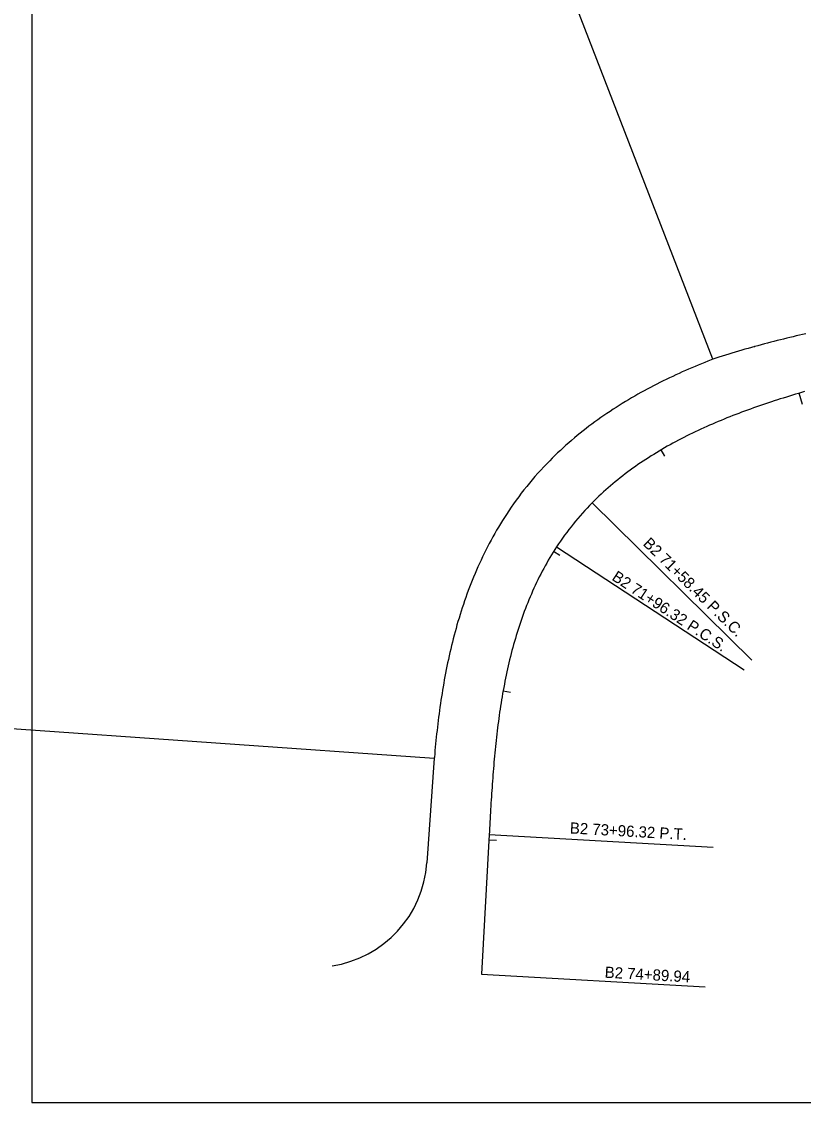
# Model space of a CAD drawing. Extents: x 7583978 to 7589962, y 550226 to 553847.
# Drawn here: x 7588230 to 7588753, y 550226 to 550949 of the extents above; entities that cross this region are included whole.
import ezdxf

# ---------------------------------------------------------------- set-up
doc = ezdxf.new("R2010")
doc.units = 0
for name, color, linetype in [('#plot_shape', 7, 'Continuous'), ('Default', 7, 'Continuous'), ('P_RDWY_ALIGN_Main', 7, 'Continuous'), ('P_RDWY_ALIGN_MainTx', 7, 'Continuous'), ('P_RDWY_ALIGN_Ramp', 7, 'Continuous'), ('P_RDWY_ALIGN_RampTic', 7, 'Continuous'), ('P_RDWY_ALIGN_RampTx', 7, 'Continuous')]:
    doc.layers.add(name, color=color, linetype=linetype)

msp = doc.modelspace()

# ---------------------------------------------------------------- linework, layer by layer
at = {"layer": '#plot_shape'}
msp.add_lwpolyline([(7588237.1, 551265.36), (7588237.1, 550226.04), (7589430.93, 550226.04), (7589430.93, 550741.48), (7589962.46, 551428.79), (7589291.08, 551428.4), (7589291.08, 551261.86)], close=True, dxfattribs=at)
at = {"layer": 'Default'}
for p, q in [((7588692.65, 550723.11), (7588512.21, 551189.41)), ((7588007.56, 550491.18), (7588506.35, 550456.35))]:
    msp.add_line(p, q, dxfattribs=at)
at = {"layer": 'P_RDWY_ALIGN_Main'}
for p, q in [((7588744.17, 550737.67), (7588742.04, 550737.15)), ((7588746.29, 550738.19), (7588744.17, 550737.67)), ((7588748.42, 550738.7), (7588746.29, 550738.19)), ((7588750.53, 550739.2), (7588748.42, 550738.7)), ((7588752.65, 550739.7), (7588750.53, 550739.2)), ((7588754.76, 550740.2), (7588752.65, 550739.7)), ((7588716.27, 550730.36), (7588714.1, 550729.75)), ((7588718.43, 550730.97), (7588716.27, 550730.36)), ((7588720.59, 550731.57), (7588718.43, 550730.97)), ((7588722.75, 550732.16), (7588720.59, 550731.57)), ((7588724.9, 550732.75), (7588722.75, 550732.16)), ((7588727.06, 550733.32), (7588724.9, 550732.75)), ((7588729.21, 550733.89), (7588727.06, 550733.32)), ((7588731.35, 550734.45), (7588729.21, 550733.89)), ((7588733.5, 550735), (7588731.35, 550734.45)), ((7588735.64, 550735.55), (7588733.5, 550735)), ((7588737.78, 550736.09), (7588735.64, 550735.55)), ((7588739.91, 550736.62), (7588737.78, 550736.09)), ((7588742.04, 550737.15), (7588739.91, 550736.62)), ((7588692.65, 550723.11), (7588691.45, 550722.64)), ((7588694.53, 550723.73), (7588692.65, 550723.11)), ((7588696.71, 550724.44), (7588694.53, 550723.73)), ((7588698.89, 550725.14), (7588696.71, 550724.44)), ((7588701.07, 550725.83), (7588698.89, 550725.14)), ((7588703.25, 550726.51), (7588701.07, 550725.83)), ((7588705.42, 550727.18), (7588703.25, 550726.51)), ((7588707.59, 550727.83), (7588705.42, 550727.18)), ((7588709.76, 550728.48), (7588707.59, 550727.83)), ((7588711.93, 550729.12), (7588709.76, 550728.48)), ((7588714.1, 550729.75), (7588711.93, 550729.12)), ((7588676.45, 550716.48), (7588674.31, 550715.55)), ((7588678.59, 550717.4), (7588676.45, 550716.48)), ((7588680.73, 550718.31), (7588678.59, 550717.4)), ((7588682.87, 550719.2), (7588680.73, 550718.31)), ((7588685.02, 550720.08), (7588682.87, 550719.2)), ((7588687.16, 550720.95), (7588685.02, 550720.08)), ((7588689.3, 550721.8), (7588687.16, 550720.95)), ((7588691.45, 550722.64), (7588689.3, 550721.8)), ((7588659.37, 550708.6), (7588657.25, 550707.54)), ((7588661.5, 550709.63), (7588659.37, 550708.6)), ((7588663.63, 550710.66), (7588661.5, 550709.63)), ((7588665.76, 550711.67), (7588663.63, 550710.66)), ((7588667.9, 550712.66), (7588665.76, 550711.67)), ((7588670.03, 550713.64), (7588667.9, 550712.66)), ((7588672.17, 550714.6), (7588670.03, 550713.64)), ((7588674.31, 550715.55), (7588672.17, 550714.6)), ((7588646.68, 550702.01), (7588644.57, 550700.85)), ((7588648.78, 550703.15), (7588646.68, 550702.01)), ((7588650.89, 550704.27), (7588648.78, 550703.15)), ((7588653.01, 550705.38), (7588650.89, 550704.27)), ((7588655.13, 550706.47), (7588653.01, 550705.38)), ((7588657.25, 550707.54), (7588655.13, 550706.47)), ((7588634.14, 550694.79), (7588632.07, 550693.53)), ((7588636.21, 550696.04), (7588634.14, 550694.79)), ((7588638.3, 550697.27), (7588636.21, 550696.04)), ((7588640.38, 550698.49), (7588638.3, 550697.27)), ((7588642.48, 550699.68), (7588640.38, 550698.49)), ((7588644.57, 550700.85), (7588642.48, 550699.68)), ((7588621.82, 550686.89), (7588619.79, 550685.51)), ((7588623.85, 550688.26), (7588621.82, 550686.89)), ((7588625.89, 550689.61), (7588623.85, 550688.26)), ((7588627.95, 550690.93), (7588625.89, 550689.61)), ((7588630, 550692.24), (7588627.95, 550690.93)), ((7588632.07, 550693.53), (7588630, 550692.24)), ((7588611.77, 550679.75), (7588609.79, 550678.26)), ((7588613.76, 550681.22), (7588611.77, 550679.75)), ((7588615.76, 550682.67), (7588613.76, 550681.22)), ((7588617.77, 550684.1), (7588615.76, 550682.67)), ((7588619.79, 550685.51), (7588617.77, 550684.1)), ((7588603.91, 550673.66), (7588601.98, 550672.08)), ((7588605.86, 550675.22), (7588603.91, 550673.66)), ((7588607.82, 550676.75), (7588605.86, 550675.22)), ((7588609.79, 550678.26), (7588607.82, 550676.75)), ((7588594.36, 550665.55), (7588592.49, 550663.87)), ((7588596.24, 550667.22), (7588594.36, 550665.55)), ((7588598.14, 550668.86), (7588596.24, 550667.22)), ((7588600.05, 550670.49), (7588598.14, 550668.86)), ((7588601.98, 550672.08), (7588600.05, 550670.49)), ((7588586.96, 550658.66), (7588585.15, 550656.89)), ((7588588.79, 550660.42), (7588586.96, 550658.66)), ((7588590.63, 550662.16), (7588588.79, 550660.42)), ((7588592.49, 550663.87), (7588590.63, 550662.16)), ((7588585.15, 550656.89), (7588583.51, 550655.24)), ((7588551.91, 550615.21), (7588550.58, 550613.05)), ((7588553.26, 550617.35), (7588551.91, 550615.21)), ((7588554.52, 550619.3), (7588553.26, 550617.35)), ((7588547.99, 550608.7), (7588546.74, 550606.52)), ((7588549.27, 550610.88), (7588547.99, 550608.7)), ((7588550.58, 550613.05), (7588549.27, 550610.88)), ((7588543.13, 550599.91), (7588541.97, 550597.69)), ((7588544.31, 550602.12), (7588543.13, 550599.91)), ((7588545.51, 550604.32), (7588544.31, 550602.12)), ((7588546.74, 550606.52), (7588545.51, 550604.32)), ((7588539.73, 550593.23), (7588538.65, 550590.99)), ((7588540.84, 550595.46), (7588539.73, 550593.23)), ((7588541.97, 550597.69), (7588540.84, 550595.46)), ((7588536.55, 550586.49), (7588535.53, 550584.24)), ((7588537.59, 550588.74), (7588536.55, 550586.49)), ((7588538.65, 550590.99), (7588537.59, 550588.74)), ((7588533.57, 550579.71), (7588532.62, 550577.44)), ((7588534.54, 550581.97), (7588533.57, 550579.71)), ((7588535.53, 550584.24), (7588534.54, 550581.97)), ((7588530.79, 550572.88), (7588529.91, 550570.6)), ((7588531.7, 550575.16), (7588530.79, 550572.88)), ((7588532.62, 550577.44), (7588531.7, 550575.16)), ((7588528.2, 550566.03), (7588527.38, 550563.74)), ((7588529.05, 550568.32), (7588528.2, 550566.03)), ((7588529.91, 550570.6), (7588529.05, 550568.32)), ((7588525.04, 550556.86), (7588524.3, 550554.56)), ((7588525.8, 550559.16), (7588525.04, 550556.86)), ((7588526.58, 550561.45), (7588525.8, 550559.16)), ((7588527.38, 550563.74), (7588526.58, 550561.45)), ((7588522.87, 550549.97), (7588522.18, 550547.67)), ((7588523.57, 550552.27), (7588522.87, 550549.97)), ((7588524.3, 550554.56), (7588523.57, 550552.27)), ((7588520.86, 550543.07), (7588520.23, 550540.77)), ((7588521.51, 550545.37), (7588520.86, 550543.07)), ((7588522.18, 550547.67), (7588521.51, 550545.37)), ((7588519.02, 550536.16), (7588518.44, 550533.87)), ((7588519.62, 550538.46), (7588519.02, 550536.16)), ((7588520.23, 550540.77), (7588519.62, 550538.46)), ((7588517.32, 550529.27), (7588516.79, 550526.97)), ((7588517.87, 550531.57), (7588517.32, 550529.27)), ((7588518.44, 550533.87), (7588517.87, 550531.57)), ((7588515.77, 550522.38), (7588515.28, 550520.09)), ((7588516.27, 550524.68), (7588515.77, 550522.38)), ((7588516.79, 550526.97), (7588516.27, 550524.68)), ((7588513.9, 550513.22), (7588513.47, 550510.94)), ((7588514.34, 550515.51), (7588513.9, 550513.22)), ((7588514.8, 550517.8), (7588514.34, 550515.51)), ((7588515.28, 550520.09), (7588514.8, 550517.8)), ((7588512.64, 550506.37), (7588512.25, 550504.09)), ((7588513.05, 550508.65), (7588512.64, 550506.37)), ((7588513.47, 550510.94), (7588513.05, 550508.65)), ((7588511.5, 550499.54), (7588511.14, 550497.27)), ((7588511.87, 550501.82), (7588511.5, 550499.54)), ((7588512.25, 550504.09), (7588511.87, 550501.82)), ((7588510.46, 550492.74), (7588510.14, 550490.48)), ((7588510.8, 550495.01), (7588510.46, 550492.74)), ((7588511.14, 550497.27), (7588510.8, 550495.01)), ((7588509.52, 550485.97), (7588509.23, 550483.72)), ((7588509.83, 550488.23), (7588509.52, 550485.97)), ((7588510.14, 550490.48), (7588509.83, 550488.23)), ((7588508.68, 550479.23), (7588508.41, 550476.99)), ((7588508.95, 550481.47), (7588508.68, 550479.23)), ((7588509.23, 550483.72), (7588508.95, 550481.47)), ((7588507.67, 550470.29), (7588507.44, 550468.06)), ((7588507.91, 550472.52), (7588507.67, 550470.29)), ((7588508.16, 550474.75), (7588507.91, 550472.52)), ((7588508.41, 550476.99), (7588508.16, 550474.75)), ((7588507, 550463.62), (7588506.8, 550461.41)), ((7588507.22, 550465.84), (7588507, 550463.62)), ((7588507.44, 550468.06), (7588507.22, 550465.84)), ((7588506.35, 550456.35), (7588501.45, 550386.26)), ((7588506.4, 550456.99), (7588506.35, 550456.35)), ((7588506.59, 550459.2), (7588506.4, 550456.99)), ((7588506.8, 550461.41), (7588506.59, 550459.2))]:
    msp.add_line(p, q, dxfattribs=at)
for centre, radius, start, end in [((7588747.91, 550492.98), 230.99, 135.37515, 146.84604), ((7588426.63, 550391.48), 75, 278.68725, 356.00603)]:
    msp.add_arc(centre, radius, start, end, dxfattribs=at)
at = {"layer": 'P_RDWY_ALIGN_MainTx'}
for centre in [(7588744.17, 550737.67), (7588746.29, 550738.19), (7588748.42, 550738.7), (7588750.53, 550739.2), (7588752.65, 550739.7), (7588716.27, 550730.36), (7588718.43, 550730.97), (7588720.59, 550731.57), (7588722.75, 550732.16), (7588724.9, 550732.75), (7588727.06, 550733.32), (7588729.21, 550733.89), (7588731.35, 550734.45), (7588733.5, 550735), (7588735.64, 550735.55), (7588737.78, 550736.09), (7588739.91, 550736.62), (7588742.04, 550737.15), (7588692.65, 550723.11), (7588694.53, 550723.73), (7588696.71, 550724.44), (7588698.89, 550725.14), (7588701.07, 550725.83), (7588703.25, 550726.51), (7588705.42, 550727.18), (7588707.59, 550727.83), (7588709.76, 550728.48), (7588711.93, 550729.12), (7588714.1, 550729.75), (7588676.45, 550716.48), (7588678.59, 550717.4), (7588680.73, 550718.31), (7588682.87, 550719.2), (7588685.02, 550720.08), (7588687.16, 550720.95), (7588689.3, 550721.8), (7588691.45, 550722.64), (7588659.37, 550708.6), (7588661.5, 550709.63), (7588663.63, 550710.66), (7588665.76, 550711.67), (7588667.9, 550712.66), (7588670.03, 550713.64), (7588672.17, 550714.6), (7588674.31, 550715.55), (7588646.68, 550702.01), (7588648.78, 550703.15), (7588650.89, 550704.27), (7588653.01, 550705.38), (7588655.13, 550706.47), (7588657.25, 550707.54), (7588634.14, 550694.79), (7588636.21, 550696.04), (7588638.3, 550697.27), (7588640.38, 550698.49), (7588642.48, 550699.68), (7588644.57, 550700.85), (7588621.82, 550686.89), (7588623.85, 550688.26), (7588625.89, 550689.61), (7588627.95, 550690.93), (7588630, 550692.24), (7588632.07, 550693.53), (7588611.77, 550679.75), (7588613.76, 550681.22), (7588615.76, 550682.67), (7588617.77, 550684.1), (7588619.79, 550685.51), (7588603.91, 550673.66), (7588605.86, 550675.22), (7588607.82, 550676.75), (7588609.79, 550678.26), (7588594.36, 550665.55), (7588596.24, 550667.22), (7588598.14, 550668.86), (7588600.05, 550670.49), (7588601.98, 550672.08), (7588586.96, 550658.66), (7588588.79, 550660.42), (7588590.63, 550662.16), (7588592.49, 550663.87), (7588583.51, 550655.24), (7588585.15, 550656.89), (7588611.85, 550627.01), (7588551.91, 550615.21), (7588553.26, 550617.35), (7588554.52, 550619.3), (7588547.99, 550608.7), (7588549.27, 550610.88), (7588550.58, 550613.05), (7588543.13, 550599.91), (7588544.31, 550602.12), (7588545.51, 550604.32), (7588546.74, 550606.52), (7588539.73, 550593.23), (7588540.84, 550595.46), (7588541.97, 550597.69), (7588588.11, 550597.58), (7588536.55, 550586.49), (7588537.59, 550588.74), (7588538.65, 550590.99), (7588533.57, 550579.71), (7588534.54, 550581.97), (7588535.53, 550584.24), (7588530.79, 550572.88), (7588531.7, 550575.16), (7588532.62, 550577.44), (7588528.2, 550566.03), (7588529.05, 550568.32), (7588529.91, 550570.6), (7588525.04, 550556.86), (7588525.8, 550559.16), (7588526.58, 550561.45), (7588527.38, 550563.74), (7588522.87, 550549.97), (7588523.57, 550552.27), (7588524.3, 550554.56), (7588520.86, 550543.07), (7588521.51, 550545.37), (7588522.18, 550547.67), (7588519.02, 550536.16), (7588519.62, 550538.46), (7588520.23, 550540.77), (7588517.32, 550529.27), (7588517.87, 550531.57), (7588518.44, 550533.87), (7588515.77, 550522.38), (7588516.27, 550524.68), (7588516.79, 550526.97), (7588513.9, 550513.22), (7588514.34, 550515.51), (7588514.8, 550517.8), (7588515.28, 550520.09), (7588512.64, 550506.37), (7588513.05, 550508.65), (7588513.47, 550510.94), (7588511.5, 550499.54), (7588511.87, 550501.82), (7588512.25, 550504.09), (7588510.46, 550492.74), (7588510.8, 550495.01), (7588511.14, 550497.27), (7588509.52, 550485.97), (7588509.83, 550488.23), (7588510.14, 550490.48), (7588508.68, 550479.23), (7588508.95, 550481.47), (7588509.23, 550483.72), (7588507.67, 550470.29), (7588507.91, 550472.52), (7588508.16, 550474.75), (7588508.41, 550476.99), (7588507, 550463.62), (7588507.22, 550465.84), (7588507.44, 550468.06), (7588506.35, 550456.35), (7588506.35, 550456.35), (7588506.4, 550456.99), (7588506.59, 550459.2), (7588506.8, 550461.41), (7588543.05, 550405.22), (7588501.45, 550386.26), (7588437.96, 550317.34), (7588537.81, 550311.75)]:
    msp.add_circle(centre, 0.00187, dxfattribs=at)
at = {"layer": 'P_RDWY_ALIGN_Ramp'}
msp.add_line((7588543.05, 550405.22), (7588537.81, 550311.75), dxfattribs=at)
for points in [[(7588753.85, 550701.47), (7588751.83, 550700.87), (7588749.82, 550700.26), (7588747.8, 550699.65), (7588745.79, 550699.04), (7588743.78, 550698.42), (7588741.77, 550697.79), (7588739.76, 550697.16), (7588737.75, 550696.53), (7588735.75, 550695.88), (7588733.74, 550695.24), (7588731.74, 550694.58), (7588729.74, 550693.92), (7588727.75, 550693.25), (7588725.75, 550692.57), (7588723.76, 550691.89), (7588721.77, 550691.2), (7588719.79, 550690.5), (7588717.8, 550689.79), (7588715.82, 550689.08), (7588713.85, 550688.36), (7588711.87, 550687.62), (7588709.9, 550686.88), (7588707.94, 550686.13), (7588705.97, 550685.37), (7588704.01, 550684.6), (7588702.06, 550683.82), (7588700.11, 550683.03), (7588698.16, 550682.23), (7588696.21, 550681.43), (7588694.28, 550680.61), (7588692.34, 550679.77), (7588690.41, 550678.93), (7588688.49, 550678.08), (7588686.57, 550677.21), (7588684.65, 550676.34), (7588682.74, 550675.45), (7588680.84, 550674.55), (7588678.94, 550673.64), (7588677.05, 550672.71), (7588675.17, 550671.78), (7588673.29, 550670.83), (7588671.42, 550669.87), (7588669.55, 550668.89), (7588667.69, 550667.9), (7588665.84, 550666.9), (7588663.99, 550665.89), (7588662.16, 550664.86), (7588660.33, 550663.81), (7588658.51, 550662.76), (7588656.7, 550661.69), (7588654.89, 550660.6), (7588653.1, 550659.5), (7588651.31, 550658.39), (7588649.53, 550657.26), (7588647.77, 550656.11), (7588646.01, 550654.96), (7588644.26, 550653.78), (7588642.52, 550652.59), (7588640.8, 550651.39), (7588639.08, 550650.17), (7588637.37, 550648.94), (7588635.68, 550647.69), (7588634, 550646.42), (7588632.33, 550645.14), (7588630.67, 550643.84), (7588629.03, 550642.53), (7588627.39, 550641.2), (7588625.77, 550639.85), (7588624.17, 550638.49), (7588622.58, 550637.11), (7588621, 550635.72), (7588619.44, 550634.31), (7588617.89, 550632.88), (7588616.35, 550631.44), (7588614.84, 550629.98), (7588613.34, 550628.5), (7588611.85, 550627.01)], [(7588588.11, 550597.58), (7588586.97, 550595.81), (7588585.84, 550594.03), (7588584.74, 550592.24), (7588583.65, 550590.44), (7588582.59, 550588.62), (7588581.54, 550586.8), (7588580.51, 550584.96), (7588579.5, 550583.11), (7588578.51, 550581.25), (7588577.54, 550579.39), (7588576.58, 550577.51), (7588575.65, 550575.62), (7588574.73, 550573.73), (7588573.83, 550571.83), (7588572.95, 550569.91), (7588572.09, 550567.99), (7588571.24, 550566.07), (7588570.41, 550564.13), (7588569.6, 550562.19), (7588568.81, 550560.24), (7588568.03, 550558.28), (7588567.27, 550556.32), (7588566.53, 550554.35), (7588565.8, 550552.37), (7588565.09, 550550.39), (7588564.39, 550548.4), (7588563.72, 550546.41), (7588563.05, 550544.41), (7588562.41, 550542.41), (7588561.77, 550540.4), (7588561.16, 550538.39), (7588560.55, 550536.37), (7588559.97, 550534.35), (7588559.4, 550532.32), (7588558.84, 550530.29), (7588558.29, 550528.26), (7588557.76, 550526.22), (7588557.25, 550524.18), (7588556.74, 550522.14), (7588556.25, 550520.09), (7588555.78, 550518.04), (7588555.31, 550515.99), (7588554.86, 550513.93), (7588554.42, 550511.87), (7588554, 550509.81), (7588553.58, 550507.74), (7588553.18, 550505.68), (7588552.79, 550503.61), (7588552.41, 550501.54), (7588552.04, 550499.47), (7588551.68, 550497.39), (7588551.34, 550495.32), (7588551, 550493.24), (7588550.67, 550491.16), (7588550.35, 550489.08), (7588550.05, 550486.99), (7588549.75, 550484.91), (7588549.46, 550482.82), (7588549.18, 550480.74), (7588548.91, 550478.65), (7588548.65, 550476.56), (7588548.39, 550474.47), (7588548.15, 550472.38), (7588547.91, 550470.29), (7588547.68, 550468.2), (7588547.45, 550466.1), (7588547.24, 550464.01), (7588547.03, 550461.91), (7588546.82, 550459.82), (7588546.63, 550457.72), (7588546.43, 550455.63), (7588546.25, 550453.53), (7588546.07, 550451.43), (7588545.9, 550449.33), (7588545.73, 550447.23), (7588545.56, 550445.14), (7588545.4, 550443.04), (7588545.25, 550440.94), (7588545.1, 550438.84), (7588544.95, 550436.74), (7588544.81, 550434.64), (7588544.67, 550432.54), (7588544.53, 550430.44), (7588544.4, 550428.33), (7588544.26, 550426.23), (7588544.14, 550424.13), (7588544.01, 550422.03), (7588543.88, 550419.93), (7588543.76, 550417.83), (7588543.64, 550415.73), (7588543.52, 550413.62), (7588543.4, 550411.52), (7588543.28, 550409.42), (7588543.16, 550407.32), (7588543.05, 550405.22)]]:
    msp.add_lwpolyline(points, dxfattribs=at)
msp.add_arc((7588747.91, 550492.98), 190.99, 135.42964, 146.79155, dxfattribs=at)
at = {"layer": 'P_RDWY_ALIGN_RampTic'}
for points in [[(7588752.65, 550692.76), (7588750.35, 550700.42)], [(7588660.61, 550658.19), (7588658.08, 550662.5)], [(7588590.36, 550591.83), (7588586.13, 550594.48)], [(7588557.24, 550500.14), (7588552.32, 550501.03)], [(7588547.83, 550401.26), (7588542.84, 550401.54)]]:
    msp.add_lwpolyline(points, dxfattribs=at)
at = {"layer": 'P_RDWY_ALIGN_RampTx'}
for points in [[(7588611.85, 550627.01), (7588718.71, 550521.74)], [(7588588.11, 550597.58), (7588713.61, 550515.43)], [(7588543.05, 550405.22), (7588692.81, 550396.82)], [(7588537.81, 550311.75), (7588687.57, 550303.35)]]:
    msp.add_lwpolyline(points, dxfattribs=at)

# ---------------------------------------------------------------- texts
for s, rotation, p in [('B2 71+58.45 P.S.C. ', 315.42964, (7588645.42, 550599.24)), ('B2 71+96.32 P.C.S. ', 326.79155, (7588624.55, 550575.85)), ('B2 73+96.32 P.T. ', 356.79155, (7588596.83, 550405.93)), ('B2 74+89.94 ', 356.79155, (7588620.13, 550309.45))]:
    msp.add_text(s, height=7.5, rotation=rotation, dxfattribs=at).set_placement(p)

doc.saveas('drawing.dxf')
